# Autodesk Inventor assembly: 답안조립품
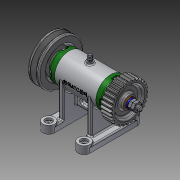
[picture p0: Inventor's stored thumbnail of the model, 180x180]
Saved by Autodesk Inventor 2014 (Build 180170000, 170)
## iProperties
Created: 2015-11
Part Number: 답안조립품
Document SubType Name: Assembly
Designer: USER
Author: USER
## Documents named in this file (16)
- C:\Users\USER\Desktop\451109V1022\답안조립품.iam
- C:\Users\USER\Desktop\451109V1022\본체.ipt
- C:\Users\USER\Desktop\451109V1022\V벨트풀리.ipt
- C:\Users\USER\Desktop\451109V1022\너트 M 8.ipt
- C:\Users\USER\Desktop\451109V1022\니플 M 6 x 0.75.ipt
- C:\Users\USER\Desktop\451109V1022\베어링 15 x 32 x 9.ipt
- C:\Users\USER\Desktop\451109V1022\볼트 M 6 x 8.ipt
- C:\Users\USER\Desktop\451109V1022\볼트 M4 x 12.ipt
- C:\Users\USER\Desktop\451109V1022\스퍼기어.ipt
- C:\Users\USER\Desktop\451109V1022\스프링와셔 8.ipt
- C:\Users\USER\Desktop\451109V1022\오일 실 15 25 7.ipt
- C:\Users\USER\Desktop\451109V1022\와셔 6x11.5.ipt
- C:\Users\USER\Desktop\451109V1022\와셔 8x17.ipt
- C:\Users\USER\Desktop\451109V1022\축.ipt
- C:\Users\USER\Desktop\451109V1022\커버.ipt
- C:\Users\USER\Desktop\451109V1022\키 3 x 3 x 12.ipt
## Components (11 placed, 3 different names)
1. V벨트풀리:1
2. KS B 2023 6002 - 15 x 32 x 9:1
3. KS B 2023 6002 - 15 x 32 x 9:2
4. ISO 4762 M4 x 12:1
5. ISO 4762 M4 x 12:2
6. ISO 4762 M4 x 12:3
7. ISO 4762 M4 x 12:4
8. ISO 4762 M4 x 12:5
9. ISO 4762 M4 x 12:6
10. ISO 4762 M4 x 12:7
11. ISO 4762 M4 x 12:8
